(* Logix 5000 project; controller ILX69PBS vendor 1 type 14 code 77 rev 16.3; software revision 16.04 *)

TASK MainTask (continuous, watchdog 500 ms) : MainProgram

MODULES
   Controller : vendor 1 type 14 code 77 (CompactLogixL32EController 0, rev 16.3)
      LocalENB : 1769-L32E Ethernet Port (CompactLogixL32Ethernet 1, rev 16.3)
      Local : CompactBus (CompactVirtualAdapter 3, rev 16.3, Input RPI 5 ms)
         PBS : vendor 309 type 12 code 6114 (Compact 1, rev 1.1, Output RPI 5 ms)
END_MODULES

TYPE ILX69PBS_CONTROL :
STRUCT
   ColdBoot : BOOL;   // Cold Boot Reset
   GetExtendedStatus : ILX69PBS_CONTROL_GETEXTENDEDDIAG;   // Get Extended Status Information Select
   SetExtendedDiagnostic : ILX69PBS_CONTROL_SETEXTENDEDDIAG;   // Set Slave Diagnostic Extended Data
END_STRUCT
END_TYPE

TYPE ILX69PBS_CONTROL_GETEXTENDEDDIAG :   // Get Extended Status Select
STRUCT
   Firmware : BOOL;   // Places Extended Firmware Data into STATUS.ExtendedStatus.Firmware
   SlaveConfig : BOOL;   // Places Extended Slave Configuration Data into STATUS.ExtendedStatus.SlaveConfiguration
   MasterConfig : BOOL;   // Places Extended Master Configuration Data into STATUS.ExtendedStatus.MasterConfiguration
   ParameterData : BOOL;   // Places Extended Parameter Data into STATUS.ExtendedStatus.ParameterData
   DPV1 : BOOL;   // Places Extended DPV1 Data into STATUS.ExtendedStatus.DPV1
END_STRUCT
END_TYPE

TYPE ILX69PBS_CONTROL_SETEXTENDEDDIAG :   // Slave Diagnostic Data
STRUCT
   Initiate : BOOL;   // Initiate Diagnostic Request
   ExtendedDiagnosticOverflow : SINT;   // Set bit 0 to indicate that more diagnostic data is available as diagnostic data can be transferred with Data below
   ExtendedDiagData : SINT[237];   // Diagnostic Data to be transferred
   MSGStatus : ILX69PBS_MESSAGE_STATUS;
END_STRUCT
END_TYPE

TYPE ILX69PBS_DATA :
STRUCT
   Output : SINT[244];   // Input Data. Profibus Output Data
   Input : SINT[244];   // Output Data. Profibus Input Data.
END_STRUCT
END_TYPE

TYPE ILX69PBS_DPV1 :   // DPV1
STRUCT
   Read : ILX69PBS_DPV1_READ;
   Write : ILX69PBS_DPV1_WRITE;
   Alarm : ILX69PBS_DPV1_ALARM;
   RWCount : SINT;
END_STRUCT
END_TYPE

TYPE ILX69PBS_DPV1_ALARM :   // DPV1 Alarm Request
STRUCT
   RequestToMaster : ILX69PBS_DPV1_ALARM_REQ_TO_MASTER;   // DPV1 Alarm Request to Master
   ResponseFromILX : ILX69PBS_DPV1_ALARM_RESPONSE_FROM_ILX;   // DPV1 Alarm Response from ILX Module
   MSGStatus : ILX69PBS_MESSAGE_STATUS;   // DPV1 Alarm MSG Status
END_STRUCT
END_TYPE

TYPE ILX69PBS_DPV1_ALARM_REQ_TO_MASTER :   // DPV1 Alarm Request to Master
STRUCT
   Initiate : BOOL;   // Initiate a DPV1 Alarm Request to the Master.
   SlotNumber : SINT;   // Slot Number for Alarm
   AlarmType : SINT;   // Alarm Type
   SequenceNumber : SINT;   // Sequence Number
   AdditionalAck : SINT;   // Additional Acknowledgement
   Specifier : SINT;   // Alarm Specifier
   Length : SINT;   // Alarm Data Length
   Data : SINT[58];   // Alarm Data
END_STRUCT
END_TYPE

TYPE ILX69PBS_DPV1_ALARM_RESPONSE_FROM_ILX :   // Alarm Response from ILX Module
STRUCT
   SlotNumber : SINT;   // Slot Number of module causing the alarm
   AlarmType : SINT;   // Type of alarm received
   SequenceNumber : SINT;   // Sequence Number
END_STRUCT
END_TYPE

TYPE ILX69PBS_DPV1_READ :   // DPV1 Read
STRUCT
   RequestFromMaster : ILX69PBS_DPV1_READ_REQ_FROM_MASTER;   // DPV1 Read Request from Master
   ResponseToMaster : ILX69PBS_DPV1_READ_RESPONE_TO_MASTER;   // DPV1 Read Response to Master
   MSGStatus : ILX69PBS_MESSAGE_STATUS;   // DPV1 Read MSG Status
END_STRUCT
END_TYPE

TYPE ILX69PBS_DPV1_READ_REQ_FROM_MASTER :   // DPV1 Read Request from Master
STRUCT
   Indication : BOOL;   // DPV1 Read Request Indication from Master
   MasterAddress : SINT;   // Master Address requesting DPV1 Read
   Slot : SINT;   // Requested Slot Number to Read
   Index : SINT;   // Requested Index to Read
   Length : SINT;   // Requested Data Length to Read
END_STRUCT
END_TYPE

TYPE ILX69PBS_DPV1_READ_RESPONE_TO_MASTER :   // DPV1 Read Response to Master
STRUCT
   Initiate : BOOL;   // Initiate a response to the Masters DPV1 read request with the associated read data.
   InhibitAutoInitiate : BOOL;   // Inhibitit Automatically Initiating a response. Master Address, Slot, Index, Length and data are copied to response.
   Slot : SINT;   // Place Requested Slot Number
   Index : SINT;   // Place Requested Index
   Length : SINT;   // Place Requested Data Length
   Data : SINT[240];   // Place Requested Data
END_STRUCT
END_TYPE

TYPE ILX69PBS_DPV1_WRITE :   // DPV1 Write
STRUCT
   RequestFromMaster : ILX69PBS_DPV1_WRITE_REQ_FROM_MASTER;   // DPV1 Write Request from Master
   ResponseToMaster : ILX69PBS_DPV1_WRITE_RESPONSE_TO_MASTER;   // DPV1 Write Response to Master
   MSGStatus : ILX69PBS_MESSAGE_STATUS;   // DPV1 Write MSG Status
END_STRUCT
END_TYPE

TYPE ILX69PBS_DPV1_WRITE_REQ_FROM_MASTER :   // DPV1 Write Request from Master
STRUCT
   Indication : BOOL;   // DPV1 Write Request Indication from Master
   MasterAddress : SINT;   // Master Address requesting DPV1 Write
   Slot : SINT;   // Request Slot Number to Write to
   Index : SINT;   // Requested Index to Write to
   Length : SINT;   // Requested Data Length to Write to
   Data : SINT[240];   // Requested Data to Write
END_STRUCT
END_TYPE

TYPE ILX69PBS_DPV1_WRITE_RESPONSE_TO_MASTER :   // DPV1 Write Response to Master
STRUCT
   Initiate : BOOL;   // Initiate a response to the Masters DPV1 write request to let the master know the write occurred.
   InhibitAutoInitiate : BOOL;   // Inhibitit Automatically Initiating a response. Master Address, Slot, Index and Length are copied to response.
   MasterAddress : SINT;   // Place Master Address
   Slot : SINT;   // Place Requested Slot Number
   Index : SINT;   // Place Requested Index
   Length : SINT;   // Place Requested Data Length
END_STRUCT
END_TYPE

TYPE ILX69PBS_MESSAGE_STATUS :   // Message Status
STRUCT
   Done : BOOL;   // Message transmitted. Response is available
   Error : BOOL;   // Last message transmitted with an error
   DoneCount : DINT;   // Response OK Count
   ErrorCount : DINT;   // Error Count
END_STRUCT
END_TYPE

TYPE ILX69PBS_MODULEDEF :   // ILX69-PBS PROFIBUS Slave Module Definition
STRUCT
   PROFIBUSDATA : ILX69PBS_DATA;   // Profibus Data
   DPV1 : ILX69PBS_DPV1;   // DPV1
   STATUS : ILX69PBS_STATUS;   // Module Status
   CONTROL : ILX69PBS_CONTROL;   // Module Control
   UTIL : ILX69PBS_UTIL;   // Util. Not used by user.
END_STRUCT
END_TYPE

TYPE ILX69PBS_STATUS :   // Status
STRUCT
   Communication : BOOL;   // Profibus communication is started and the module is engaged in cyclic data exchange with the master
   Running : BOOL;   // Running. Module is ready for communication.
   Ready : BOOL;   // Ready. Module is operational.
   Address : SINT;   // Slave Bus Address
   Identification : INT;   // Slave Identification Number. Should be 0x0EE1
   BaudRate : INT;   // Baud Rate 12000=12M 6000=6M 3000=3M 1500=1.5M 500=500k 187=187.5k 93=93.75k 9=9.6k 0=not detected
   FirmwareRevision : ILX69PBS_STATUS_FW_REVISION;   // Firmware Revision
   ExtendedStatus : ILX69PBS_STATUS_EXT;   // Extended Status Information
   ParameterDataChange : BOOL;   // Parameter Data Changed
   ConfigurationDataChange : BOOL;   // Configuration Data Changed
   InputDataLength : INT;   // Input Data Length 0-244
   OutputDataLength : INT;   // Output Data Length 0-244
   WatchdogTime : INT;   // Current Watchdog Time
   ProfibusActivityCounter : INT;   // Profibus Activity Counter
END_STRUCT
END_TYPE

TYPE ILX69PBS_STATUS_EXT :   // Extended Status Info
STRUCT
   NoneSelected : BOOL;   // Not Extended Data Selected
   FirmwareSelected : BOOL;   // Extended Firmware Data current in STATUS.ExtendedStatus.Firmware
   SlaveConfigSelected : BOOL;   // Extended Slave Configuration Data current in STATUS.ExtendedStatus.SlaveConfiguration
   MasterConfigSelected : BOOL;   // Extended Master Configuration Data current in STATUS.ExtendedStatus.MasterConfiguration
   ParameterDataSelected : BOOL;   // Extended Parameter Data current in STATUS.ExtendedStatus.ParameterData
   DPV1Selected : BOOL;   // Extended DPV1 Data current in STATUS.ExtendedStatus.PDV1
   Length : INT;   // Length of Extended Data
   Firmware : ILX69PBS_STATUS_EXT_FIRMWARE;   // Extended Firmware Info
   SlaveConfiguration : ILX69PBS_STATUS_EXT_CONFIG;   // Extended Slave Configuration Data
   MasterConfiguration : ILX69PBS_STATUS_EXT_CONFIG;   // Extended Master Configuration Data
   ParameterData : ILX69PBS_STATUS_EXT_PARAM;   // Extended Parameter Data
   DPV1 : ILX69PBS_STATUS_EXT_DPV1;   // Extended DPV1 Data
END_STRUCT
END_TYPE

TYPE ILX69PBS_STATUS_EXT_CONFIG :   // Extended Configuration Information
STRUCT
   Length : SINT;   // Number of valid configuration bytes
   Data : SINT[49];   // Configuration Bytes
END_STRUCT
END_TYPE

TYPE ILX69PBS_STATUS_EXT_DPV1 :   // DPV1 Extended Information
STRUCT
   StatusRequests : DINT;   // Number of Status Requests from User
   StatusMessagesSent : DINT;   // Number of Status Messages Sent
   NegativeStatusConfirmations : DINT;   // Number of Negative Status Confirmation to User
   DiagnosticRequests : DINT;   // Number of Diagnostic Requests from User
   DiagnosticMessagesSent : DINT;   // Number of Diagnostic Messages Sent
   NegativeDiagnosticConfirmations : DINT;   // Number of Negative Diagnostic Confirmations to User
   AlarmRequests : DINT;   // Number of Alarm Requests from User
   AlarmMessagesSent : DINT;   // Number of Alarm Messages Sent
   PositiveAlarmConfirmations : DINT;   // Number of Positive Alarm Confirmations to User
   NegativeAlarmConfirmations : DINT;   // Number of Negative Alarm Confirmations to User
   Requests : DINT;   // Number of Requests
   ImmediateNegativeConfirmations : DINT;   // Number of Immediate Negative Confirmations
   ReadWriteIndications : DINT;   // Number of Read/Write Indications to User
   PositiveReadWriteResponses : DINT;   // Number of Positive Read/Write Responses from User
   NegativeReadWriteResponses : DINT;   // Number of Negative Read/Write Responses from User
   AlarmAckIndications : DINT;   // Number of Alarm Acknowledge Indications
   AlarmAckResponses : DINT;   // Number of Alarm Acknowledge Responses
   AlarmAckErrors : DINT;   // Number of Alarm Acknowledge Errors
   ErrorResponses : DINT;   // Number of Error Responses from User
   UnexpectedErrorResponses : DINT;   // Number of Unexpected Responses from User
END_STRUCT
END_TYPE

TYPE ILX69PBS_STATUS_EXT_FIRMWARE :   // Extended Firmware Information
STRUCT
   Version : ILX69PBS_STATUS_EXT_FIRMWARE_VERSION;   // Firmware Version
   Name : ILX69PBS_STATUS_EXT_FIRMWARE_NAME;   // Firmware Name
   Date : ILX69PBS_STATUS_EXT_FIRMWARE_DATE;   // Firmware Date
END_STRUCT
END_TYPE

TYPE ILX69PBS_STATUS_EXT_FIRMWARE_DATE :   // Date
STRUCT
   Month : SINT;   // Month
   Day : SINT;   // Day
   Year : INT;   // Year
END_STRUCT
END_TYPE

TYPE ILX69PBS_STATUS_EXT_FIRMWARE_NAME :   // Name
STRUCT
   Name : SINT[64];   // Firmware Name
END_STRUCT
END_TYPE

TYPE ILX69PBS_STATUS_EXT_FIRMWARE_VERSION :   // Version
STRUCT
   Major : INT;   // Major
   Minor : INT;   // Minor
   Build : INT;   // Build
   Revision : INT;   // Revision
END_STRUCT
END_TYPE

TYPE ILX69PBS_STATUS_EXT_PARAM :   // Extended Parameter Data
STRUCT
   Length : SINT;   // Number of valid parameter bytes
   Data : SINT[32];   // Parameter Bytes
END_STRUCT
END_TYPE

TYPE ILX69PBS_STATUS_FW_REVISION :   // Firmware Major/Minor Revision
STRUCT
   FwMinor : SINT;   // Firmware Minor Revison
   FwMajor : SINT;   // Firmware Major Revison
END_STRUCT
END_TYPE

TYPE ILX69PBS_UTIL :
STRUCT
   MSG : ILX69PBS_UTIL_MSG;   // Messages
END_STRUCT
END_TYPE

TYPE ILX69PBS_UTIL_AOI :
STRUCT
   InputArray : ILX69PBS_UTIL_AOI_INPUT_ARRAY;   // Input from Module
   OutputArray : ILX69PBS_UTIL_AOI_OUTPUT_ARRAY;   // Output to Module
   InputSize : INT;
   OutputSize : INT;
   InputDataSize : INT;
   InputCopyLength : INT;
   OutputDataSize : INT;
   OutputCopyLength : INT;
   OutputCopyLastLength : INT;
   OutputConnectionSize : INT;
   UTILOutputCopyLength : INT;
   PreviousBPActivityCounter : INT;
   ReadReqMasterLengthDINT : DINT;
   AlarmReqMasterLengthDINT : DINT;
END_STRUCT
END_TYPE

TYPE ILX69PBS_UTIL_AOI_DEV_COMMAND_REGISTER :   // Device Command Register
STRUCT
   Reserved0 : BOOL;   // Reserved
   Reserved1 : BOOL;   // Reserved
   Reserved2 : BOOL;   // Reserved
   Reserved3 : BOOL;   // Reserved
   Reserved4 : BOOL;   // Reserved
   Reserved5 : BOOL;   // Application Not Ready
   Reserved6 : BOOL;   // Init ( Warm boot )
   Reset : BOOL;   // Reset ( Cold boot )
   Reserved7 : SINT;   // Reserved
   Reserved8 : SINT;   // Reserved
   ExtStaSelect : SINT;   // Extended Status Information Select 1=Firmware 2=Slave Config 3=Master Config 4=Parameter Data 5+ Reserved
END_STRUCT
END_TYPE

TYPE ILX69PBS_UTIL_AOI_DEV_STATUS_REGISTER :   // Device Status Register
STRUCT
   Reserved0 : BOOL;   // Reserved
   Reserved1 : BOOL;   // Reserved
   Reserved2 : BOOL;   // Reserved
   Reserved3 : BOOL;   // Reserved
   Reserved4 : BOOL;   // Reserved
   Communication : BOOL;   // Communication
   Running : BOOL;   // Running
   Ready : BOOL;   // Ready
   Reserved5 : SINT;   // Reserved
   Reserved6 : SINT;   // Reserved
   Reserved7 : SINT;   // Reserved
END_STRUCT
END_TYPE

TYPE ILX69PBS_UTIL_AOI_FW_REVISION :   // Firmware Major/Minor Revision
STRUCT
   FwMinor : SINT;   // Firmware Minor Revison
   FwMajor : SINT;   // Firmware Major Revison
   Reserved : INT;   // Reserved
END_STRUCT
END_TYPE

TYPE ILX69PBS_UTIL_AOI_INPUT_ARRAY :   // Input Array
STRUCT
   DeviceStatusRegister : ILX69PBS_UTIL_AOI_DEV_STATUS_REGISTER;   // Device Status
   FirmwareRev : ILX69PBS_UTIL_AOI_FW_REVISION;   // Firmware Revision and Block Size
   SlaveStatus : ILX69PBS_UTIL_AOI_SLAVE_STATUS;   // Slave Status
   InputData : SINT[244];   // PROFIBUS Output data.
END_STRUCT
END_TYPE

TYPE ILX69PBS_UTIL_AOI_OUTPUT_ARRAY :
STRUCT
   DeviceCommandRegister : ILX69PBS_UTIL_AOI_DEV_COMMAND_REGISTER;   // Command Register
   OutputData : SINT[244];   // PROFIBUS Input data.
END_STRUCT
END_TYPE

TYPE ILX69PBS_UTIL_AOI_SLAVE_STATUS :   // Slave Status Information
STRUCT
   ExtStaSelect : INT;   // 0=No Extended status inform 1=Firmware version 2=Slave Config 3=Master Config 4=Parameter data 6=Reserved
   ExtStaLen : INT;   // 0=0 Byte 1=32 Byte 2=49 Byte 3=49 Byte 4=33 Byte 6=80 Byte
   Baudrate : INT;   // 12000=12MBaud 6000=6MBaud 3000=3MBaud 1500=1.5MBaud 500=500kBaud 187=187.5kBaud 93=93.75kBaud 9=9.6kBaud 0=not detected
   Busaddress : SINT;   // 0 ... 125
   UserFlags : SINT;   // D0=Parameter data changed D1=Configuration data changed D2...D7 Dont'care
   Indent : INT;   // Should be 0x0EE1
   Reserved : INT;   // Reserved
   InputDataLen : INT;   // Legnth of input data 0 ... 244
   OutputDataLen : INT;   // Length of output data 0 ... 244
   Reserved1 : INT;   // Should be 0
   Reserved2 : SINT;   // Should be 0
   Pad : SINT;   // Reserved. Should be 0
   WatchdogTime : INT;   // Current Watch dog time. 5 ... 65535ms
   IrqCounter : INT;   // Indication of bus activity. 0 ... 0xFFFF
   DPV1RWInd : SINT;   // A Read/Write Indication has been received. Bit 0 set indicates a Read. Bit 1 set indicates a Write.
   DPV1RWIndCnt : SINT;   // Increment on every new DPV1 request
   DPV1MasterAdr : SINT;   // Address of Requesting Master
   DPV1Slot : SINT;   // Requested Slot Number
   DPV1Index : SINT;   // Requested Index
   DPV1DataLen : SINT;   // Requested Data Length
   Reserved3 : SINT;   // Reserved
   Reserved4 : SINT;   // Reserved
   ExtStatusInfo : SINT[96];   // Dependent on ExtStaSelect value
END_STRUCT
END_TYPE

TYPE ILX69PBS_UTIL_MSG :   // MSG Instructions
STRUCT
   DPV1Read : ILX69PBS_UTIL_MSG_DPV1_READ;
   DPV1Write : ILX69PBS_UTIL_MSG_DPV1_WRITE;
   DPV1Alarm : ILX69PBS_UTIL_MSG_DPV1_ALARM;
   SetExtDiag : ILX69PBS_UTIL_MSG_SETEXTDIAG;
END_STRUCT
END_TYPE

TYPE ILX69PBS_UTIL_MSG_DPV1_ALARM :   // DPV1 Alarm MSG Status, Source and Destination
STRUCT
   Source : ILX69PBS_UTIL_MSG_DPV1_ALARM_REQUEST;   // Source. Request from Master
   Destination : ILX69PBS_UTIL_MSG_DPV1_ALARM_RESPONSE;   // Destination. Response to Master
END_STRUCT
END_TYPE

TYPE ILX69PBS_UTIL_MSG_DPV1_ALARM_REQUEST :   // DPV1 Alarm Response Request
STRUCT
   Status : DINT;   // Status
   Command : DINT;   // Message Command. Set to 0x0480
   SlotNumber : SINT;   // Slot Number of data to be read
   AlarmType : SINT;   // Alarm Type
   SequenceNumber : SINT;   // Sequence Number
   AdditionalAck : SINT;   // Additional Acknowledgement
   Specifier : SINT;   // Alarm Specifier
   Length : SINT;   // Alarm Length
   Reserved1 : SINT;
   Reserved2 : SINT;
   Data : SINT[58];   // Alarm Data
END_STRUCT
END_TYPE

TYPE ILX69PBS_UTIL_MSG_DPV1_ALARM_RESPONSE :   // DPV1 Alarm Response Confirm
STRUCT
   Status : DINT;   // Status 0=OK
   Command : DINT;   // Should be 0x0485
   SlotNumber : SINT;   // Slot Number of module causing the alarm
   AlarmType : SINT;   // Type of alarm received
   SequenceNumber : SINT;   // Sequence Number
   Reserved : SINT;   // Reserved Padding byte. Set to 0.
END_STRUCT
END_TYPE

TYPE ILX69PBS_UTIL_MSG_DPV1_READ :   // DPV1 Read MSG Status, Source and Destination
STRUCT
   Source : ILX69PBS_UTIL_MSG_DPV1_READ_REQUEST;   // Source. Request from Master
   Destination : ILX69PBS_UTIL_MSG_DPV1_READ_RESPONSE;   // Destination. Response to Master
END_STRUCT
END_TYPE

TYPE ILX69PBS_UTIL_MSG_DPV1_READ_REQUEST :   // DPV1 Read Request MSG Structure
STRUCT
   Status : DINT;   // Status
   Command : DINT;   // Message Command. Set to 0x0485
   SlotNumber : SINT;   // Slot Number
   Index : SINT;   // Index
   Length : SINT;   // Length
   Reserved1 : SINT;   // Reserved
   ErrorDecode : SINT;   // Error Code Classifying Fault
   ErrorCode1 : SINT;   // Detailed Error Code
   ErrorCode2 : SINT;   // User Specific Error Code
   Reserved2 : SINT;   // Reserved
   Data : SINT[240];   // Read Request Data
END_STRUCT
END_TYPE

TYPE ILX69PBS_UTIL_MSG_DPV1_READ_RESPONSE :   // DPV1 Read Response MSG
STRUCT
   Status : DINT;   // Status
   Command : DINT;   // Should be 0x0485
   SlotNumber : SINT;   // Slot Number
   Index : SINT;   // Index
   Length : SINT;   // Length
   Reserved : SINT;   // Reserved
END_STRUCT
END_TYPE

TYPE ILX69PBS_UTIL_MSG_DPV1_WRITE :   // DPV1 Write MSG Status, Source and Destination
STRUCT
   Source : ILX69PBS_UTIL_MSG_DPV1_WRITE_REQUEST;   // Source. Request from Master
   Destination : ILX69PBS_UTIL_MSG_DPV1_WRITE_RESPONSE;   // Destination. Response to Master
END_STRUCT
END_TYPE

TYPE ILX69PBS_UTIL_MSG_DPV1_WRITE_REQUEST :   // DPV1 Write Request
STRUCT
   Status : DINT;   // Status 0=OK
   Command : DINT;   // Should return 0x0487
   SlotNumber : SINT;   // Slot Number
   Index : SINT;   // Index
   Length : SINT;   // Length
   Reserved1 : SINT;   // Reserved
   ErrorDecode : SINT;   // Error Code Classifying Fault
   ErrorCode1 : SINT;   // Error Code 1
   ErrorCode2 : SINT;   // Error Code 2
   Reserved2 : SINT;   // Reserved
END_STRUCT
END_TYPE

TYPE ILX69PBS_UTIL_MSG_DPV1_WRITE_RESPONSE :   // DPV1 Write Response
STRUCT
   Status : DINT;   // Status
   Command : DINT;   // Message Command. Set to 0x0487
   SlotNumber : SINT;   // Slot Number
   Index : SINT;   // Index
   Length : SINT;   // Length
   Reserved1 : SINT;   // Reserved
   ErrorDecode : SINT;   // Error Code Classifying Fault
   ErrorCode1 : SINT;   // Detailed Error Code
   ErrorCode2 : SINT;   // User Specific Error Code
   Reserved2 : SINT;   // Reserved
   Data : SINT[240];   // Write Data
END_STRUCT
END_TYPE

TYPE ILX69PBS_UTIL_MSG_SETEXTDIAG :   // Slave Diagnostic Data
STRUCT
   Source : ILX69PBS_UTIL_MSG_SETEXTDIAG_REQUEST;   // Request
   Destination : ILX69PBS_UTIL_MSG_SETEXTDIAG_RESPONSE;
END_STRUCT
END_TYPE

TYPE ILX69PBS_UTIL_MSG_SETEXTDIAG_REQUEST :   // Slave Diagnostic Request
STRUCT
   Status : DINT;   // Slave Status
   Command : DINT;   // Message Command. Set to 0x040E
   ExtendedDiagnosticOverflow : SINT;   // Set bit 0 to indicate that more diagnostic data is available as diagnostic data can be transferred with Data below
   Reserved1 : SINT;   // Reserved
   Reserved2 : SINT;
   Reserved3 : SINT;
   ExtendedDiagData : SINT[237];   // Diagnostic Data to be transferred
END_STRUCT
END_TYPE

TYPE ILX69PBS_UTIL_MSG_SETEXTDIAG_RESPONSE :   // Slave Diagnostic Response
STRUCT
   Status : DINT;   // Slave Status
   Command : DINT;   // Message Command. Reposnds with 0x040F
END_STRUCT
END_TYPE

ADD_ON_INSTRUCTION AOIILX69PBS   (* revision 1.1, ExecutePrescan *)
// Add-On instruction for ILX69-PBS ProSoft module
// Revision note:
// v1.1 - Fixed found typo errors in UDT
// v1.0 - Initial Revision
VAR_IN_OUT
   ILX69PBS : ILX69PBS_MODULEDEF; {required}
   Connection_Input : INT[190]; {required}
        [0].5   // Communication
        [0].6   // Running
        [0].7   // Ready
   Connection_Output : INT[124]; {required}
   MSGDPV1Read : MESSAGE; {required}   // DPV1 Read Message
   MSGDPV1Write : MESSAGE; {required}   // DPV1 Write Message
   MSGDPV1Alarm : MESSAGE; {required}   // DPV1 Alarm Request Message
   MSGSetExtDiag : MESSAGE; {required}   // Slave Diagnostic Request Message
END_VAR
VAR
   UTIL : ILX69PBS_UTIL_AOI;
END_VAR

ROUTINE Logic   (* ladder *)
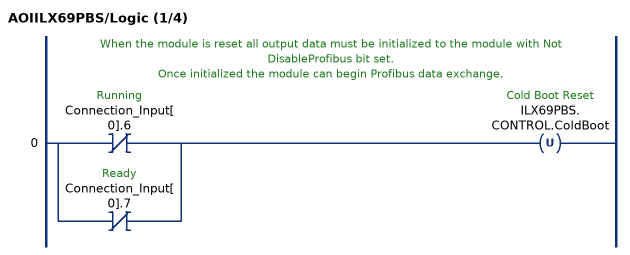
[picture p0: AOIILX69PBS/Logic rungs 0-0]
   // When the module is reset all output data must be initialized to the module with Not DisableProfibus bit set.
   // Once initialized the module can begin Profibus data exchange.
   0: [XIO(Connection_Input[0].6) ,XIO(Connection_Input[0].7) ]OTU(ILX69PBS.CONTROL.ColdBoot);
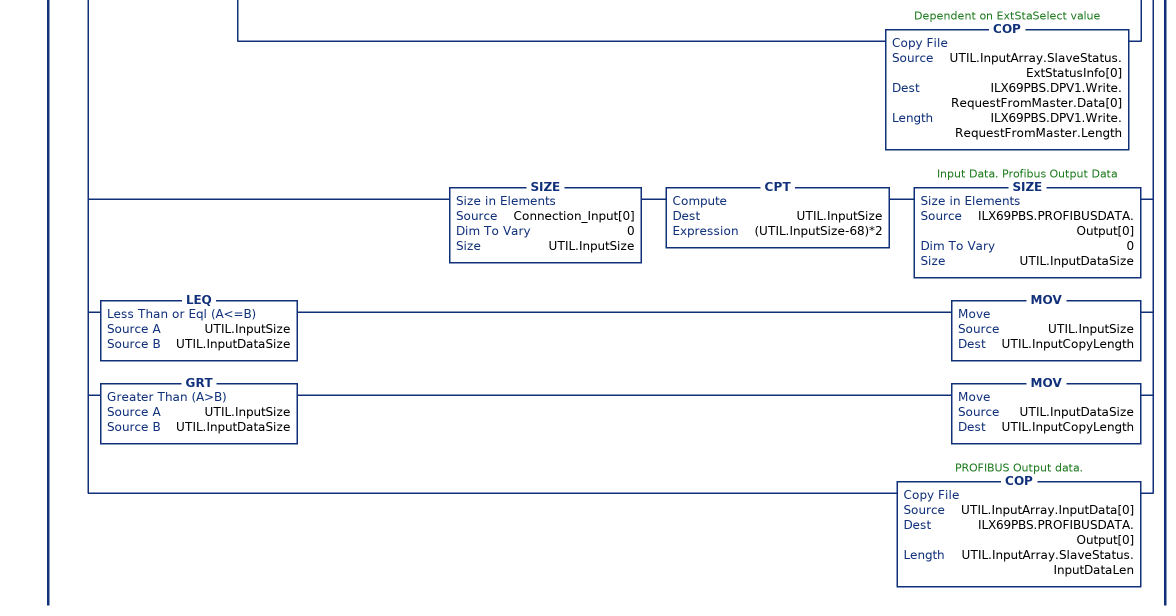
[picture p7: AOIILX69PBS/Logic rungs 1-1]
   // Handle Input Data
   1: COP(Connection_Input[0],UTIL.InputArray,1)[MOV(UTIL.InputArray.SlaveStatus.IrqCounter,UTIL.PreviousBPActivityCounter) ,[[XIC(UTIL.InputArray.DeviceStatusRegister.Communication) XIO(ILX69PBS.STATUS.Communication) OTL(ILX69PBS.STATUS.Communication) ,XIO(UTIL.InputArray.DeviceStatusRegister.Communication) XIC(ILX69PBS.STATUS.Communication) OTU(ILX69PBS.STATUS.Communication) ] ,[XIC(UTIL.InputArray.DeviceStatusRegister.Running) XIO(ILX69PBS.STATUS.Running) OTL(ILX69PBS.STATUS.Running) ,XIO(UTIL.InputArray.DeviceStatusRegister.Running) XIC(ILX69PBS.STATUS.Running) OTU(ILX69PBS.STATUS.Running) ] ,[XIC(UTIL.InputArray.DeviceStatusRegister.Ready) XIO(ILX69PBS.STATUS.Ready) OTL(ILX69PBS.STATUS.Ready) ,XIO(UTIL.InputArray.DeviceStatusRegister.Ready) XIC(ILX69PBS.STATUS.Ready) OTU(ILX69PBS.STATUS.Ready) ] ] ,COP(UTIL.InputArray.FirmwareRev,ILX69PBS.STATUS.FirmwareRevision,1) ,LIM(0,UTIL.InputArray.SlaveStatus.ExtStaSelect,6) [OTU(ILX69PBS.STATUS.ExtendedStatus.NoneSelected) ,OTU(ILX69PBS.STATUS.ExtendedStatus.FirmwareSelected) ,OTU(ILX69PBS.STATUS.ExtendedStatus.SlaveConfigSelected) ,OTU(ILX69PBS.STATUS.ExtendedStatus.MasterConfigSelected) ,OTU(ILX69PBS.STATUS.ExtendedStatus.ParameterDataSelected) ,OTU(ILX69PBS.STATUS.ExtendedStatus.DPV1Selected) ] [XIO(UTIL.InputArray.SlaveStatus.ExtStaSelect.2) XIO(UTIL.InputArray.SlaveStatus.ExtStaSelect.1) XIO(UTIL.InputArray.SlaveStatus.ExtStaSelect.0) OTL(ILX69PBS.STATUS.ExtendedStatus.NoneSelected) ,XIO(UTIL.InputArray.SlaveStatus.ExtStaSelect.2) XIO(UTIL.InputArray.SlaveStatus.ExtStaSelect.1) XIC(UTIL.InputArray.SlaveStatus.ExtStaSelect.0) OTL(ILX69PBS.STATUS.ExtendedStatus.FirmwareSelected) ,XIO(UTIL.InputArray.SlaveStatus.ExtStaSelect.2) XIC(UTIL.InputArray.SlaveStatus.ExtStaSelect.1) XIO(UTIL.InputArray.SlaveStatus.ExtStaSelect.0) OTL(ILX69PBS.STATUS.ExtendedStatus.SlaveConfigSelected) ,XIO(UTIL.InputArray.SlaveStatus.ExtStaSelect.2) XIC(UTIL.InputArray.SlaveStatus.ExtStaSelect.1) XIC(UTIL.InputArray.SlaveStatus.ExtStaSelect.0) OTL(ILX69PBS.STATUS.ExtendedStatus.MasterConfigSelected) ,XIC(UTIL.InputArray.SlaveStatus.ExtStaSelect.2) XIO(UTIL.InputArray.SlaveStatus.ExtStaSelect.1) XIO(UTIL.InputArray.SlaveStatus.ExtStaSelect.0) OTL(ILX69PBS.STATUS.ExtendedStatus.ParameterDataSelected) ,XIC(UTIL.InputArray.SlaveStatus.ExtStaSelect.2) XIC(UTIL.InputArray.SlaveStatus.ExtStaSelect.1) XIO(UTIL.InputArray.SlaveStatus.ExtStaSelect.0) OTL(ILX69PBS.STATUS.ExtendedStatus.DPV1Selected) ] ,[MOV(UTIL.InputArray.SlaveStatus.ExtStaLen,ILX69PBS.STATUS.ExtendedStatus.Length) ,XIC(ILX69PBS.STATUS.ExtendedStatus.FirmwareSelected) [COP(UTIL.InputArray.SlaveStatus.ExtStatusInfo[0],ILX69PBS.STATUS.ExtendedStatus.Firmware.Version.Major,4) ,COP(UTIL.InputArray.SlaveStatus.ExtStatusInfo[12],ILX69PBS.STATUS.ExtendedStatus.Firmware.Name.Name[0],64) ,COP(UTIL.InputArray.SlaveStatus.ExtStatusInfo[10],ILX69PBS.STATUS.ExtendedStatus.Firmware.Date.Month,1) COP(UTIL.InputArray.SlaveStatus.ExtStatusInfo[11],ILX69PBS.STATUS.ExtendedStatus.Firmware.Date.Day,1) COP(UTIL.InputArray.SlaveStatus.ExtStatusInfo[8],ILX69PBS.STATUS.ExtendedStatus.Firmware.Date.Year,1) ] ,XIC(ILX69PBS.STATUS.ExtendedStatus.SlaveConfigSelected) [MOV(ILX69PBS.STATUS.ExtendedStatus.Length,ILX69PBS.STATUS.ExtendedStatus.SlaveConfiguration.Length) ,COP(UTIL.InputArray.SlaveStatus.ExtStatusInfo[0],ILX69PBS.STATUS.ExtendedStatus.SlaveConfiguration.Data[0],ILX69PBS.STATUS.ExtendedStatus.Length) ] ,XIC(ILX69PBS.STATUS.ExtendedStatus.MasterConfigSelected) [MOV(ILX69PBS.STATUS.ExtendedStatus.Length,ILX69PBS.STATUS.ExtendedStatus.MasterConfiguration.Length) ,COP(UTIL.InputArray.SlaveStatus.ExtStatusInfo[0],ILX69PBS.STATUS.ExtendedStatus.MasterConfiguration.Data[0],ILX69PBS.STATUS.ExtendedStatus.Length) ] ,XIC(ILX69PBS.STATUS.ExtendedStatus.ParameterDataSelected) [MOV(ILX69PBS.STATUS.ExtendedStatus.Length,ILX69PBS.STATUS.ExtendedStatus.ParameterData.Length) ,COP(UTIL.InputArray.SlaveStatus.ExtStatusInfo[0],ILX69PBS.STATUS.ExtendedStatus.ParameterData.Data[0],ILX69PBS.STATUS.ExtendedStatus.Length) ] ,XIC(ILX69PBS.STATUS.ExtendedStatus.DPV1Selected) CPT(ILX69PBS.STATUS.ExtendedStatus.Length,UTIL.InputArray.SlaveStatus.ExtStaLen/4) COP(UTIL.InputArray.SlaveStatus.ExtStatusInfo[0],ILX69PBS.STATUS.ExtendedStatus.DPV1.StatusRequests,ILX69PBS.STATUS.ExtendedStatus.Length) MOV(UTIL.InputArray.SlaveStatus.ExtStaLen,ILX69PBS.STATUS.ExtendedStatus.Length) ] ,MOV(UTIL.InputArray.SlaveStatus.Baudrate,ILX69PBS.STATUS.BaudRate) MOV(UTIL.InputArray.SlaveStatus.Busaddress,ILX69PBS.STATUS.Address) ,[[XIC(UTIL.InputArray.SlaveStatus.UserFlags.0) XIO(ILX69PBS.STATUS.ParameterDataChange) OTL(ILX69PBS.STATUS.ParameterDataChange) ,XIO(UTIL.InputArray.SlaveStatus.UserFlags.0) XIC(ILX69PBS.STATUS.ParameterDataChange) OTU(ILX69PBS.STATUS.ParameterDataChange) ] ,[XIC(UTIL.InputArray.SlaveStatus.UserFlags.1) XIO(ILX69PBS.STATUS.ConfigurationDataChange) OTL(ILX69PBS.STATUS.ConfigurationDataChange) ,XIO(UTIL.InputArray.SlaveStatus.UserFlags.1) XIC(ILX69PBS.STATUS.ConfigurationDataChange) OTU(ILX69PBS.STATUS.ConfigurationDataChange) ] ] ,MOV(UTIL.InputArray.SlaveStatus.Indent,ILX69PBS.STATUS.Identification) ,MOV(UTIL.InputArray.SlaveStatus.InputDataLen,ILX69PBS.STATUS.InputDataLength) MOV(UTIL.InputArray.SlaveStatus.OutputDataLen,ILX69PBS.STATUS.OutputDataLength) ,MOV(UTIL.InputArray.SlaveStatus.WatchdogTime,ILX69PBS.STATUS.WatchdogTime) MOV(UTIL.InputArray.SlaveStatus.IrqCounter,ILX69PBS.STATUS.ProfibusActivityCounter) ,[[XIC(UTIL.InputArray.SlaveStatus.DPV1RWInd.0) XIO(ILX69PBS.DPV1.Read.RequestFromMaster.Indication) OTL(ILX69PBS.DPV1.Read.RequestFromMaster.Indication) ,XIO(UTIL.InputArray.SlaveStatus.DPV1RWInd.0) XIC(ILX69PBS.DPV1.Read.RequestFromMaster.Indication) OTU(ILX69PBS.DPV1.Read.RequestFromMaster.Indication) ] ,[XIC(UTIL.InputArray.SlaveStatus.DPV1RWInd.1) XIO(ILX69PBS.DPV1.Write.RequestFromMaster.Indication) OTL(ILX69PBS.DPV1.Write.RequestFromMaster.Indication) ,XIO(UTIL.InputArray.SlaveStatus.DPV1RWInd.1) XIC(ILX69PBS.DPV1.Write.RequestFromMaster.Indication) OTU(ILX69PBS.DPV1.Write.RequestFromMaster.Indication) ] ] ,MOV(UTIL.InputArray.SlaveStatus.DPV1RWIndCnt,ILX69PBS.DPV1.RWCount) ,[XIC(ILX69PBS.DPV1.Read.RequestFromMaster.Indication) COP(UTIL.InputArray.SlaveStatus.DPV1MasterAdr,ILX69PBS.DPV1.Read.RequestFromMaster.MasterAddress,4) ,XIC(ILX69PBS.DPV1.Write.RequestFromMaster.Indication) [COP(UTIL.InputArray.SlaveStatus.DPV1MasterAdr,ILX69PBS.DPV1.Write.RequestFromMaster.MasterAddress,4) ,COP(UTIL.InputArray.SlaveStatus.ExtStatusInfo[0],ILX69PBS.DPV1.Write.RequestFromMaster.Data[0],ILX69PBS.DPV1.Write.RequestFromMaster.Length) ] ] ,[SIZE(Connection_Input[0],0,UTIL.InputSize) CPT(UTIL.InputSize,(UTIL.InputSize-68)*2) SIZE(ILX69PBS.PROFIBUSDATA.Output[0],0,UTIL.InputDataSize) ,[LEQ(UTIL.InputSize,UTIL.InputDataSize) MOV(UTIL.InputSize,UTIL.InputCopyLength) ,GRT(UTIL.InputSize,UTIL.InputDataSize) MOV(UTIL.InputDataSize,UTIL.InputCopyLength) ] ] ,COP(UTIL.InputArray.InputData[0],ILX69PBS.PROFIBUSDATA.Output[0],UTIL.InputArray.SlaveStatus.InputDataLen) ];
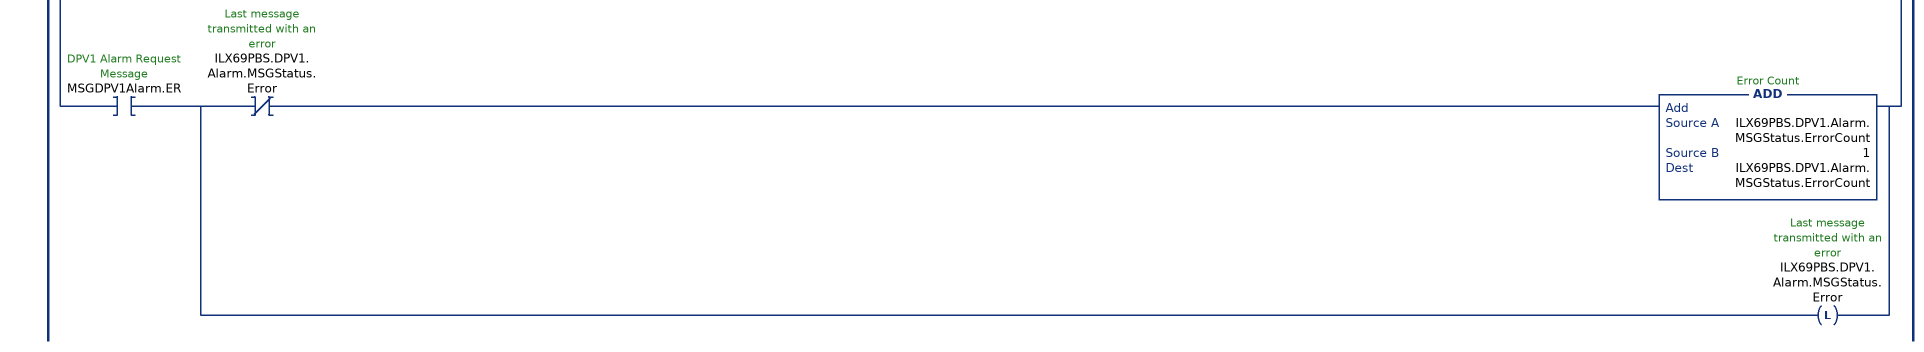
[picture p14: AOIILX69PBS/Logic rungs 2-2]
   // Message Handling
   2: [[XIC(ILX69PBS.CONTROL.SetExtendedDiagnostic.Initiate) [XIC(MSGSetExtDiag.DN) ,XIC(MSGSetExtDiag.ER) ] [MOV(16#040E,ILX69PBS.UTIL.MSG.SetExtDiag.Source.Command) ,MOV(ILX69PBS.CONTROL.SetExtendedDiagnostic.ExtendedDiagnosticOverflow,ILX69PBS.UTIL.MSG.SetExtDiag.Source.ExtendedDiagnosticOverflow) ,COP(ILX69PBS.CONTROL.SetExtendedDiagnostic.ExtendedDiagData[0],ILX69PBS.UTIL.MSG.SetExtDiag.Source.ExtendedDiagData[0],237) ,MSG(MSGSetExtDiag) ,OTU(ILX69PBS.CONTROL.SetExtendedDiagnostic.Initiate) ,OTU(ILX69PBS.CONTROL.SetExtendedDiagnostic.MSGStatus.Error) ,OTU(ILX69PBS.CONTROL.SetExtendedDiagnostic.MSGStatus.Done) ] ,XIC(MSGSetExtDiag.DN) [XIO(ILX69PBS.CONTROL.SetExtendedDiagnostic.MSGStatus.Done) ADD(ILX69PBS.CONTROL.SetExtendedDiagnostic.MSGStatus.DoneCount,1,ILX69PBS.CONTROL.SetExtendedDiagnostic.MSGStatus.DoneCount) ,OTL(ILX69PBS.CONTROL.SetExtendedDiagnostic.MSGStatus.Done) ] ,XIC(MSGSetExtDiag.ER) [XIO(ILX69PBS.CONTROL.SetExtendedDiagnostic.MSGStatus.Error) ADD(ILX69PBS.CONTROL.SetExtendedDiagnostic.MSGStatus.ErrorCount,1,ILX69PBS.CONTROL.SetExtendedDiagnostic.MSGStatus.ErrorCount) ,OTL(ILX69PBS.CONTROL.SetExtendedDiagnostic.MSGStatus.Error) ] ] ,[XIC(ILX69PBS.DPV1.Read.RequestFromMaster.Indication) [XIC(MSGDPV1Read.DN) ,XIC(MSGDPV1Read.ER) ] [XIC(ILX69PBS.DPV1.Read.ResponseToMaster.Initiate) ,XIO(ILX69PBS.DPV1.Read.ResponseToMaster.InhibitAutoInitiate) [COP(ILX69PBS.DPV1.Read.RequestFromMaster.Slot,ILX69PBS.UTIL.MSG.DPV1Read.Source.SlotNumber,3) ,COP(ILX69PBS.DPV1.Read.ResponseToMaster.Data[0],ILX69PBS.UTIL.MSG.DPV1Read.Source.Data[0],ILX69PBS.DPV1.Read.RequestFromMaster.Length) ] ] [MVM(ILX69PBS.DPV1.Read.RequestFromMaster.Length,16#FF,UTIL.ReadReqMasterLengthDINT) CPT(MSGDPV1Read.REQ_LEN,16+UTIL.ReadReqMasterLengthDINT) [LES(MSGDPV1Read.REQ_LEN,16) MOV(16,MSGDPV1Read.REQ_LEN) ,GRT(MSGDPV1Read.REQ_LEN,256) MOV(256,MSGDPV1Read.REQ_LEN) ] ,[MOV(16#0485,ILX69PBS.UTIL.MSG.DPV1Read.Source.Command) ,MSG(MSGDPV1Read) ,OTU(ILX69PBS.DPV1.Read.ResponseToMaster.Initiate) ,OTU(ILX69PBS.DPV1.Read.MSGStatus.Error) ,OTU(ILX69PBS.DPV1.Read.MSGStatus.Done) ] ] ,XIC(MSGDPV1Read.DN) [XIO(ILX69PBS.DPV1.Read.MSGStatus.Done) ADD(ILX69PBS.DPV1.Read.MSGStatus.DoneCount,1,ILX69PBS.DPV1.Read.MSGStatus.DoneCount) ,OTL(ILX69PBS.DPV1.Read.MSGStatus.Done) ] ,XIC(MSGDPV1Read.ER) [XIO(ILX69PBS.DPV1.Read.MSGStatus.Error) ADD(ILX69PBS.DPV1.Read.MSGStatus.ErrorCount,1,ILX69PBS.DPV1.Read.MSGStatus.ErrorCount) ,OTL(ILX69PBS.DPV1.Read.MSGStatus.Error) ] ] ,[XIC(ILX69PBS.DPV1.Write.RequestFromMaster.Indication) [XIC(MSGDPV1Write.DN) ,XIC(MSGDPV1Write.ER) ] [XIC(ILX69PBS.DPV1.Write.ResponseToMaster.Initiate) ,XIO(ILX69PBS.DPV1.Write.ResponseToMaster.InhibitAutoInitiate) [COP(ILX69PBS.DPV1.Write.RequestFromMaster.Slot,ILX69PBS.UTIL.MSG.DPV1Write.Source.SlotNumber,3) ,COP(ILX69PBS.UTIL.MSG.DPV1Write.Destination.Data[0],ILX69PBS.DPV1.Write.RequestFromMaster.Data[0],ILX69PBS.DPV1.Write.RequestFromMaster.Length) ] ] [MOV(16#0487,ILX69PBS.UTIL.MSG.DPV1Write.Source.Command) ,MSG(MSGDPV1Write) ,OTU(ILX69PBS.DPV1.Write.ResponseToMaster.Initiate) ,OTU(ILX69PBS.DPV1.Write.MSGStatus.Error) ,OTU(ILX69PBS.DPV1.Write.MSGStatus.Done) ] ,XIC(MSGDPV1Write.DN) [XIO(ILX69PBS.DPV1.Write.MSGStatus.Done) ADD(ILX69PBS.DPV1.Write.MSGStatus.DoneCount,1,ILX69PBS.DPV1.Write.MSGStatus.DoneCount) ,OTL(ILX69PBS.DPV1.Write.MSGStatus.Done) ] ,XIC(MSGDPV1Write.ER) [XIO(ILX69PBS.DPV1.Write.MSGStatus.Error) ADD(ILX69PBS.DPV1.Write.MSGStatus.ErrorCount,1,ILX69PBS.DPV1.Write.MSGStatus.ErrorCount) ,OTL(ILX69PBS.DPV1.Write.MSGStatus.Error) ] ] ,[XIC(ILX69PBS.DPV1.Alarm.RequestToMaster.Initiate) [MVM(ILX69PBS.DPV1.Alarm.RequestToMaster.Length,16#FF,UTIL.AlarmReqMasterLengthDINT) CPT(MSGDPV1Alarm.REQ_LEN,16+UTIL.AlarmReqMasterLengthDINT) [LES(MSGDPV1Alarm.REQ_LEN,16) MOV(16,MSGDPV1Alarm.REQ_LEN) ,GRT(MSGDPV1Alarm.REQ_LEN,74) MOV(74,MSGDPV1Alarm.REQ_LEN) ] ,MOV(16#0480,ILX69PBS.UTIL.MSG.DPV1Alarm.Source.Command) COP(ILX69PBS.DPV1.Alarm.RequestToMaster.SlotNumber,ILX69PBS.UTIL.MSG.DPV1Alarm.Source.SlotNumber,6) COP(ILX69PBS.DPV1.Alarm.RequestToMaster.Data[0],ILX69PBS.UTIL.MSG.DPV1Alarm.Source.Data[0],ILX69PBS.DPV1.Alarm.RequestToMaster.Length) ,MSG(MSGDPV1Alarm) ,OTU(ILX69PBS.DPV1.Alarm.RequestToMaster.Initiate) ,OTU(ILX69PBS.DPV1.Alarm.MSGStatus.Error) ,OTU(ILX69PBS.DPV1.Alarm.MSGStatus.Done) ] ,XIC(MSGDPV1Alarm.DN) [XIO(ILX69PBS.DPV1.Alarm.MSGStatus.Done) ADD(ILX69PBS.DPV1.Alarm.MSGStatus.DoneCount,1,ILX69PBS.DPV1.Alarm.MSGStatus.DoneCount) ,OTL(ILX69PBS.DPV1.Alarm.MSGStatus.Done) ] ,XIC(MSGDPV1Alarm.ER) [XIO(ILX69PBS.DPV1.Alarm.MSGStatus.Error) ADD(ILX69PBS.DPV1.Alarm.MSGStatus.ErrorCount,1,ILX69PBS.DPV1.Alarm.MSGStatus.ErrorCount) ,OTL(ILX69PBS.DPV1.Alarm.MSGStatus.Error) ] ] ];
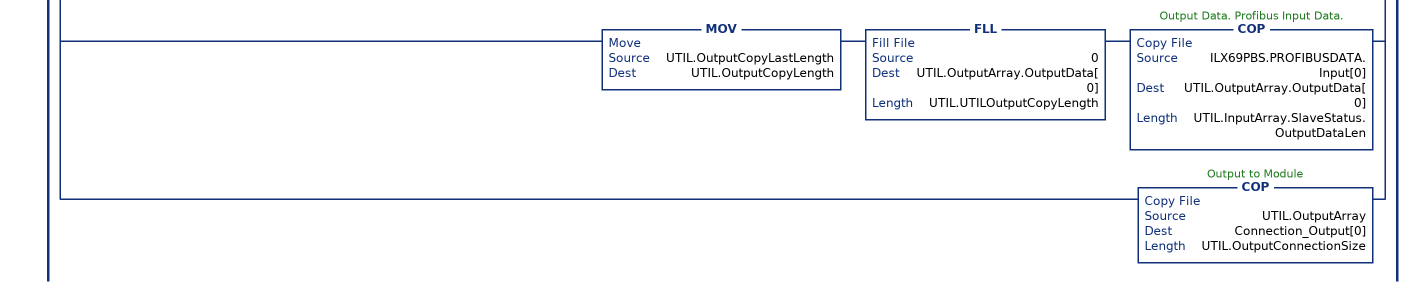
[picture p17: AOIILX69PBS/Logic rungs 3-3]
   // Handle Output Data
   3: [[[XIC(ILX69PBS.CONTROL.ColdBoot) XIO(UTIL.OutputArray.DeviceCommandRegister.Reset) OTL(UTIL.OutputArray.DeviceCommandRegister.Reset) ,XIO(ILX69PBS.CONTROL.ColdBoot) XIC(UTIL.OutputArray.DeviceCommandRegister.Reset) OTU(UTIL.OutputArray.DeviceCommandRegister.Reset) ] ,[XIO(ILX69PBS.CONTROL.GetExtendedStatus.Firmware) XIO(ILX69PBS.CONTROL.GetExtendedStatus.SlaveConfig) XIO(ILX69PBS.CONTROL.GetExtendedStatus.MasterConfig) XIO(ILX69PBS.CONTROL.GetExtendedStatus.ParameterData) MOV(0,UTIL.OutputArray.DeviceCommandRegister.ExtStaSelect) ,XIC(ILX69PBS.CONTROL.GetExtendedStatus.Firmware) MOV(1,UTIL.OutputArray.DeviceCommandRegister.ExtStaSelect) ,XIC(ILX69PBS.CONTROL.GetExtendedStatus.SlaveConfig) MOV(2,UTIL.OutputArray.DeviceCommandRegister.ExtStaSelect) ,XIC(ILX69PBS.CONTROL.GetExtendedStatus.MasterConfig) MOV(3,UTIL.OutputArray.DeviceCommandRegister.ExtStaSelect) ,XIC(ILX69PBS.CONTROL.GetExtendedStatus.ParameterData) MOV(4,UTIL.OutputArray.DeviceCommandRegister.ExtStaSelect) ,XIC(ILX69PBS.CONTROL.GetExtendedStatus.DPV1) MOV(6,UTIL.OutputArray.DeviceCommandRegister.ExtStaSelect) ] ] ,[SIZE(Connection_Output[0],0,UTIL.OutputConnectionSize) CPT(UTIL.OutputSize,UTIL.OutputConnectionSize-2) SIZE(UTIL.OutputArray.OutputData[0],0,UTIL.UTILOutputCopyLength) SIZE(ILX69PBS.PROFIBUSDATA.Input[0],0,UTIL.OutputDataSize) DIV(UTIL.OutputDataSize,2,UTIL.OutputDataSize) ,[LEQ(UTIL.OutputSize,UTIL.OutputDataSize) MOV(UTIL.OutputSize,UTIL.OutputCopyLastLength) ,GRT(UTIL.OutputSize,UTIL.OutputDataSize) MOV(UTIL.OutputDataSize,UTIL.OutputCopyLastLength) ] ] ,MOV(UTIL.OutputCopyLastLength,UTIL.OutputCopyLength) FLL(0,UTIL.OutputArray.OutputData[0],UTIL.UTILOutputCopyLength) COP(ILX69PBS.PROFIBUSDATA.Input[0],UTIL.OutputArray.OutputData[0],UTIL.InputArray.SlaveStatus.OutputDataLen) ,COP(UTIL.OutputArray,Connection_Output[0],UTIL.OutputConnectionSize) ];
END_ROUTINE

ROUTINE Prescan   (* ladder *)
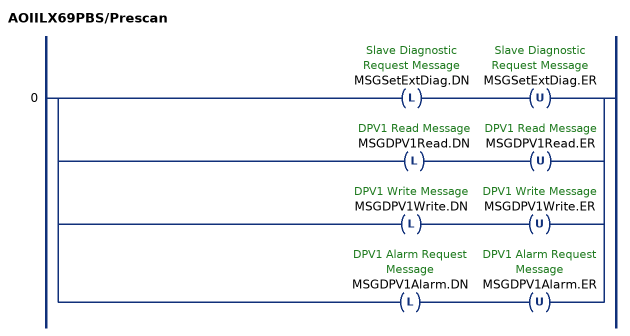
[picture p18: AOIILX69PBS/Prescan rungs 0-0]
   0: [OTL(MSGSetExtDiag.DN) OTU(MSGSetExtDiag.ER) ,OTL(MSGDPV1Read.DN) OTU(MSGDPV1Read.ER) ,OTL(MSGDPV1Write.DN) OTU(MSGDPV1Write.ER) ,OTL(MSGDPV1Alarm.DN) OTU(MSGDPV1Alarm.ER) ];
END_ROUTINE
END_ADD_ON_INSTRUCTION

VAR_GLOBAL   (* controller tags *)
   AOIILX69PBS : AOIILX69PBS;
   ILX69PBS : ILX69PBS_MODULEDEF;
   ILX69PBS_MSGDPV1Alarm : MESSAGE;   // DPV1 Alarm Request Message
        MessageParameters(ServiceCode := 16#0064, LocalElement := ILX69PBS.UTIL.MSG.DPV1Alarm.Source, DestinationTag := ILX69PBS.UTIL.MSG.DPV1Alarm.Destination, ...)
   ILX69PBS_MSGDPV1Read : MESSAGE;   // DPV1 Read Message
        MessageParameters(ServiceCode := 16#0064, LocalElement := ILX69PBS.UTIL.MSG.DPV1Read.Source, DestinationTag := ILX69PBS.UTIL.MSG.DPV1Read.Destination, ...)
   ILX69PBS_MSGDPV1Write : MESSAGE;   // DPV1 Write Message
        MessageParameters(ServiceCode := 16#0064, LocalElement := ILX69PBS.UTIL.MSG.DPV1Write.Source, DestinationTag := ILX69PBS.UTIL.MSG.DPV1Write.Destination, ...)
   ILX69PBS_MSGSetExtDiag : MESSAGE;   // Slave Diagnostic Request Message
        MessageParameters(ServiceCode := 16#0064, LocalElement := ILX69PBS.UTIL.MSG.SetExtDiag.Source, DestinationTag := ILX69PBS.UTIL.MSG.SetExtDiag.Destination, ...)
END_VAR

PROGRAM MainProgram   (* main routine MainRoutine *)

ROUTINE MainRoutine   (* ladder *)
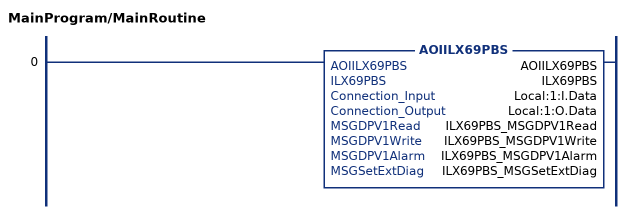
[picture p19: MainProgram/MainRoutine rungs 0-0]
   0: AOIILX69PBS(AOIILX69PBS,ILX69PBS,Local:1:I.Data,Local:1:O.Data,ILX69PBS_MSGDPV1Read,ILX69PBS_MSGDPV1Write,ILX69PBS_MSGDPV1Alarm,ILX69PBS_MSGSetExtDiag);
END_ROUTINE
END_PROGRAM
